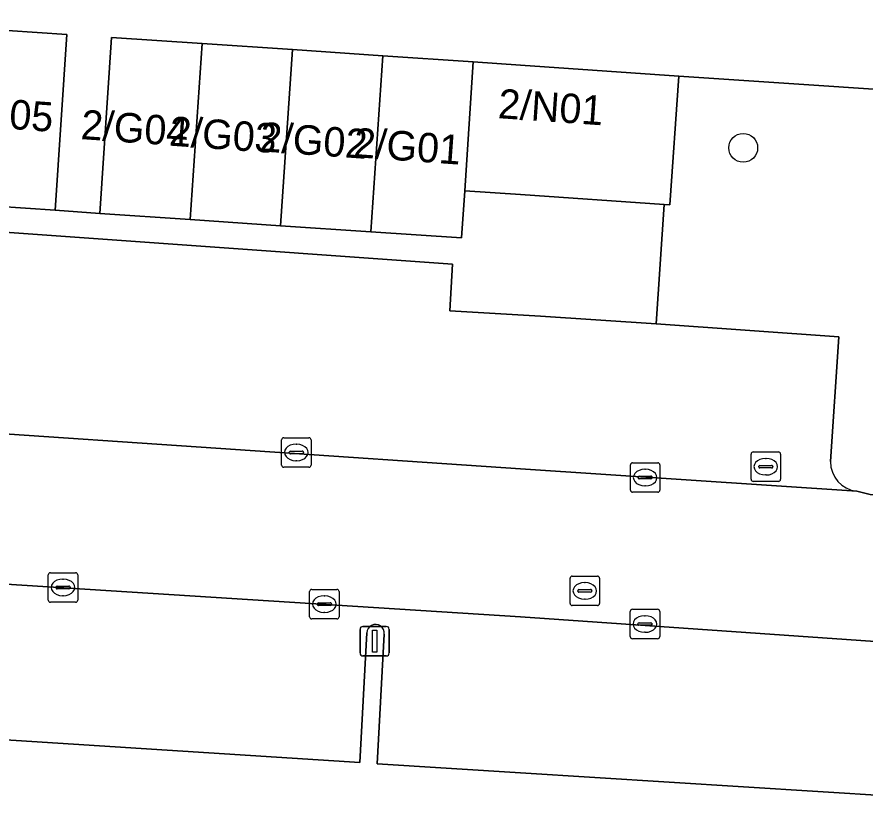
# Model space of a CAD drawing. Extents: x 161848 to 162726, y 385382 to 386521.
# Drawn here: x 161982.91 to 162011.69, y 385866.63 to 385893.06 of the extents above; entities that cross this region are included whole.
import ezdxf

# ---------------------------------------------------------------- set-up
doc = ezdxf.new("R2010")
doc.units = 0
for name, color, linetype in [('IMGEO_Boom', 7, 'Continuous'), ('IMGEO_Brandkraan', 7, 'Continuous'), ('IMGEO_Erf', 7, 'Continuous'), ('IMGEO_Groenvoorziening', 7, 'Continuous'), ('IMGEO_Kolk', 7, 'Continuous'), ('IMGEO_Lichtmast', 7, 'Continuous'), ('IMGEO_Pand', 7, 'Continuous'), ('IMGEO_Pand_nummerreeks', 7, 'Continuous'), ('IMGEO_Parkeervlak_open', 7, 'Continuous'), ('IMGEO_Rijbaan_lokaal_open', 7, 'Continuous'), ('IMGEO_Rioolput', 7, 'Continuous'), ('IMGEO_Voetpad_open', 7, 'Continuous')]:
    doc.layers.add(name, color=color, linetype=linetype)

msp = doc.modelspace()

# ---------------------------------------------------------------- linework, layer by layer
at = {"layer": 'IMGEO_Boom'}
msp.add_circle((162007.553, 385888.622), 0.489, dxfattribs=at)
at = {"layer": 'IMGEO_Brandkraan'}
for p, q in [((162007.818, 385877.377), (162007.818, 385878.229)), ((162007.893, 385878.303), (162008.745, 385878.303)), ((162008.819, 385878.229), (162008.819, 385877.377)), ((162008.12, 385877.846), (162008.518, 385877.846)), ((162008.306, 385878.083), (162008.331, 385878.083)), ((162008.077, 385877.797), (162008.077, 385877.809)), ((162008.515, 385877.76), (162008.117, 385877.76)), ((162008.561, 385877.809), (162008.561, 385877.797)), ((162008.745, 385877.303), (162007.893, 385877.303)), ((162008.329, 385877.523), (162008.304, 385877.523))]:
    msp.add_line(p, q, dxfattribs=at)
for points in [[(162007.818, 385877.377), (162007.818, 385878.229)], [(162007.893, 385878.303), (162008.745, 385878.303)], [(162008.819, 385878.229), (162008.819, 385877.377)], [(162008.745, 385877.303), (162007.893, 385877.303)]]:
    msp.add_lwpolyline(points, dxfattribs=at)
for centre, radius, start, end in [((162007.895, 385878.227), 0.0765, 91.552, 178.448), ((162007.895, 385878.227), 0.0765, 91.552, 178.448), ((162008.743, 385878.227), 0.0765, 1.552, 88.448), ((162008.743, 385878.227), 0.0765, 1.552, 88.448), ((162008.117, 385877.806), 0.0403, 85.8775, 175.7526), ((162008.522, 385877.808), 0.0386, 1.7309, 96.639), ((162008.114, 385877.796), 0.0366, 178.938, 274.7102), ((162008.518, 385877.803), 0.043, 264.8664, 352.4533), ((162007.895, 385877.379), 0.0765, 181.552, 268.448), ((162007.895, 385877.379), 0.0765, 181.552, 268.448), ((162008.743, 385877.379), 0.0765, 271.552, 358.448), ((162008.743, 385877.379), 0.0765, 271.552, 358.448)]:
    msp.add_arc(centre, radius, start, end, dxfattribs=at)
for centre, major_axis, ratio, start_param, end_param in [((162008.305, 385877.803), (-0.387, 0.002), 0.722429, 4.712389, 7.853982), ((162008.33, 385877.803), (-0.39, 0.002), 0.717154, 1.570796, 4.712389)]:
    msp.add_ellipse(centre, major_axis=major_axis, ratio=ratio, start_param=start_param, end_param=end_param, dxfattribs=at)
at = {"layer": 'IMGEO_Erf'}
msp.add_lwpolyline([(161964.413, 385968.919), (161959.389, 385894.166), (161966.417, 385893.698), (161969.448, 385893.493), (161972.48, 385893.288), (161975.512, 385893.084), (161978.543, 385892.879), (161981.575, 385892.674), (161984.606, 385892.469), (161984.206, 385886.51), (161985.726, 385886.39), (161986.122, 385892.367), (161989.19, 385892.16), (161992.258, 385891.952), (161995.326, 385891.745), (161998.394, 385891.537), (162000, 385891.426), (162005.37, 385891.056), (162016.387, 385890.314), (162021.428, 385965.253)], dxfattribs=at)
at = {"layer": 'IMGEO_Groenvoorziening'}
msp.add_lwpolyline([(162011.406, 385876.97), (162011.857, 385876.854), (162014.191, 385876.692), (162015.241, 385876.631), (162015.467, 385876.641), (162016.387, 385890.314), (162005.37, 385891.056), (162005.066, 385886.685), (162004.876, 385886.698), (162004.598, 385882.651), (162010.797, 385882.214), (162010.509, 385877.98)], dxfattribs=at)
msp.add_arc((162011.532, 385877.985), 1.023, 180.2916, 262.9262, dxfattribs=at)
at = {"layer": 'IMGEO_Kolk'}
for p, q in [((161991.891, 385877.859), (161991.891, 385878.711)), ((161991.966, 385878.785), (161992.818, 385878.785)), ((161992.892, 385878.711), (161992.892, 385877.859)), ((161992.379, 385878.565), (161992.404, 385878.565)), ((161992.15, 385878.279), (161992.15, 385878.291)), ((161992.588, 385878.242), (161992.19, 385878.242)), ((161992.193, 385878.328), (161992.591, 385878.328)), ((161992.634, 385878.291), (161992.634, 385878.279)), ((161992.402, 385878.005), (161992.377, 385878.005)), ((162003.724, 385877.009), (162003.724, 385877.861)), ((162003.799, 385877.935), (162004.651, 385877.935)), ((162004.725, 385877.861), (162004.725, 385877.009)), ((161992.818, 385877.785), (161991.966, 385877.785)), ((162004.212, 385877.715), (162004.237, 385877.715)), ((162003.983, 385877.429), (162003.983, 385877.441)), ((162004.421, 385877.392), (162004.023, 385877.392)), ((162004.026, 385877.478), (162004.424, 385877.478)), ((162004.467, 385877.441), (162004.467, 385877.429)), ((162004.235, 385877.155), (162004.21, 385877.155)), ((162004.651, 385876.935), (162003.799, 385876.935)), ((161983.973, 385873.28), (161983.973, 385874.132)), ((161984.048, 385874.206), (161984.9, 385874.206)), ((161984.974, 385874.132), (161984.974, 385873.28)), ((161984.461, 385873.986), (161984.486, 385873.986)), ((161984.232, 385873.7), (161984.232, 385873.712)), ((161984.67, 385873.663), (161984.272, 385873.663)), ((161984.275, 385873.749), (161984.673, 385873.749)), ((161984.716, 385873.712), (161984.716, 385873.7)), ((161992.841, 385872.713), (161992.841, 385873.565)), ((161992.916, 385873.639), (161993.768, 385873.639)), ((161993.842, 385873.565), (161993.842, 385872.713)), ((161984.484, 385873.426), (161984.459, 385873.426)), ((161993.329, 385873.419), (161993.354, 385873.419)), ((161984.9, 385873.206), (161984.048, 385873.206)), ((161993.1, 385873.133), (161993.1, 385873.145)), ((161993.538, 385873.096), (161993.14, 385873.096)), ((161993.143, 385873.182), (161993.541, 385873.182)), ((161993.584, 385873.145), (161993.584, 385873.133)), ((162003.792, 385872.964), (162004.644, 385872.964)), ((161993.352, 385872.859), (161993.327, 385872.859)), ((162003.717, 385872.038), (162003.717, 385872.89)), ((162004.205, 385872.744), (162004.23, 385872.744)), ((162004.718, 385872.89), (162004.718, 385872.038)), ((161993.768, 385872.639), (161992.916, 385872.639)), ((162003.976, 385872.458), (162003.976, 385872.47)), ((162004.414, 385872.421), (162004.016, 385872.421)), ((162004.019, 385872.507), (162004.417, 385872.507)), ((162004.46, 385872.47), (162004.46, 385872.458)), ((162004.228, 385872.184), (162004.203, 385872.184)), ((162004.644, 385871.964), (162003.792, 385871.964))]:
    msp.add_line(p, q, dxfattribs=at)
for points in [[(161991.891, 385877.859), (161991.891, 385878.711)], [(161991.966, 385878.785), (161992.818, 385878.785)], [(161992.892, 385878.711), (161992.892, 385877.859)], [(162003.724, 385877.009), (162003.724, 385877.861)], [(162003.799, 385877.935), (162004.651, 385877.935)], [(162004.725, 385877.861), (162004.725, 385877.009)], [(161992.818, 385877.785), (161991.966, 385877.785)], [(162004.651, 385876.935), (162003.799, 385876.935)], [(161983.973, 385873.28), (161983.973, 385874.132)], [(161984.048, 385874.206), (161984.9, 385874.206)], [(161984.974, 385874.132), (161984.974, 385873.28)], [(161992.841, 385872.713), (161992.841, 385873.565)], [(161992.916, 385873.639), (161993.768, 385873.639)], [(161993.842, 385873.565), (161993.842, 385872.713)], [(161984.9, 385873.206), (161984.048, 385873.206)], [(162003.792, 385872.964), (162004.644, 385872.964)], [(162003.717, 385872.038), (162003.717, 385872.89)], [(162004.718, 385872.89), (162004.718, 385872.038)], [(161993.768, 385872.639), (161992.916, 385872.639)], [(162004.644, 385871.964), (162003.792, 385871.964)]]:
    msp.add_lwpolyline(points, dxfattribs=at)
for centre, radius, start, end in [((161991.968, 385878.709), 0.0765, 91.552, 178.448), ((161991.968, 385878.709), 0.0765, 91.552, 178.448), ((161992.816, 385878.709), 0.0765, 1.552, 88.448), ((161992.816, 385878.709), 0.0765, 1.552, 88.448), ((161992.19, 385878.288), 0.0403, 85.8775, 175.7526), ((161992.187, 385878.278), 0.0366, 178.938, 274.7102), ((161992.591, 385878.285), 0.043, 264.8664, 352.4533), ((161992.595, 385878.29), 0.0386, 1.7309, 96.639), ((161991.968, 385877.861), 0.0765, 181.552, 268.448), ((161991.968, 385877.861), 0.0765, 181.552, 268.448), ((161992.816, 385877.861), 0.0765, 271.552, 358.448), ((161992.816, 385877.861), 0.0765, 271.552, 358.448), ((162003.801, 385877.859), 0.0765, 91.552, 178.448), ((162003.801, 385877.859), 0.0765, 91.552, 178.448), ((162004.649, 385877.859), 0.0765, 1.552, 88.448), ((162004.649, 385877.859), 0.0765, 1.552, 88.448), ((162004.023, 385877.438), 0.0403, 85.8775, 175.7526), ((162004.02, 385877.428), 0.0366, 178.938, 274.7102), ((162004.424, 385877.435), 0.043, 264.8664, 352.4533), ((162004.428, 385877.44), 0.0386, 1.7309, 96.639), ((162003.801, 385877.011), 0.0765, 181.552, 268.448), ((162003.801, 385877.011), 0.0765, 181.552, 268.448), ((162004.649, 385877.011), 0.0765, 271.552, 358.448), ((162004.649, 385877.011), 0.0765, 271.552, 358.448), ((161984.05, 385874.13), 0.0765, 91.552, 178.448), ((161984.05, 385874.13), 0.0765, 91.552, 178.448), ((161984.898, 385874.13), 0.0765, 1.552, 88.448), ((161984.898, 385874.13), 0.0765, 1.552, 88.448), ((161984.272, 385873.709), 0.0403, 85.8775, 175.7526), ((161984.269, 385873.699), 0.0366, 178.938, 274.7102), ((161984.673, 385873.706), 0.043, 264.8664, 352.4533), ((161984.677, 385873.711), 0.0386, 1.7309, 96.639), ((161992.918, 385873.563), 0.0765, 91.552, 178.448), ((161992.918, 385873.563), 0.0765, 91.552, 178.448), ((161993.766, 385873.563), 0.0765, 1.552, 88.448), ((161993.766, 385873.563), 0.0765, 1.552, 88.448), ((161984.05, 385873.282), 0.0765, 181.552, 268.448), ((161984.05, 385873.282), 0.0765, 181.552, 268.448), ((161984.898, 385873.282), 0.0765, 271.552, 358.448), ((161984.898, 385873.282), 0.0765, 271.552, 358.448), ((161993.14, 385873.142), 0.0403, 85.8775, 175.7526), ((161993.137, 385873.132), 0.0366, 178.938, 274.7102), ((161993.541, 385873.139), 0.043, 264.8664, 352.4533), ((161993.545, 385873.144), 0.0386, 1.7309, 96.639), ((162003.794, 385872.888), 0.0765, 91.552, 178.448), ((162003.794, 385872.888), 0.0765, 91.552, 178.448), ((162004.642, 385872.888), 0.0765, 1.552, 88.448), ((162004.642, 385872.888), 0.0765, 1.552, 88.448), ((161992.918, 385872.715), 0.0765, 181.552, 268.448), ((161992.918, 385872.715), 0.0765, 181.552, 268.448), ((161993.766, 385872.715), 0.0765, 271.552, 358.448), ((161993.766, 385872.715), 0.0765, 271.552, 358.448), ((162004.016, 385872.467), 0.0403, 85.8775, 175.7526), ((162004.013, 385872.457), 0.0366, 178.938, 274.7102), ((162004.417, 385872.464), 0.043, 264.8664, 352.4533), ((162004.421, 385872.469), 0.0386, 1.7309, 96.639), ((162003.794, 385872.04), 0.0765, 181.552, 268.448), ((162003.794, 385872.04), 0.0765, 181.552, 268.448), ((162004.642, 385872.04), 0.0765, 271.552, 358.448), ((162004.642, 385872.04), 0.0765, 271.552, 358.448)]:
    msp.add_arc(centre, radius, start, end, dxfattribs=at)
for centre, major_axis, ratio, start_param, end_param in [((161992.378, 385878.285), (-0.387, 0.002), 0.722429, 4.712389, 7.853982), ((161992.403, 385878.285), (-0.39, 0.002), 0.717154, 1.570796, 4.712389), ((162004.211, 385877.435), (-0.387, 0.002), 0.722429, 4.712389, 7.853982), ((162004.236, 385877.435), (-0.39, 0.002), 0.717154, 1.570796, 4.712389), ((161984.46, 385873.706), (-0.387, 0.002), 0.722429, 4.712389, 7.853982), ((161984.485, 385873.706), (-0.39, 0.002), 0.717154, 1.570796, 4.712389), ((161993.328, 385873.139), (-0.387, 0.002), 0.722429, 4.712389, 7.853982), ((161993.353, 385873.139), (-0.39, 0.002), 0.717154, 1.570796, 4.712389), ((162004.204, 385872.464), (-0.387, 0.002), 0.722429, 4.712389, 7.853982), ((162004.229, 385872.464), (-0.39, 0.002), 0.717154, 1.570796, 4.712389)]:
    msp.add_ellipse(centre, major_axis=major_axis, ratio=ratio, start_param=start_param, end_param=end_param, dxfattribs=at)
at = {"layer": 'IMGEO_Lichtmast'}
for p, q in [((161994.651, 385872.383), (161995.441, 385872.383)), ((161995.441, 385872.383), (161994.651, 385872.383)), ((161994.551, 385871.483), (161994.551, 385872.283)), ((161994.551, 385872.283), (161994.551, 385871.483)), ((161995.541, 385872.283), (161995.541, 385871.483)), ((161995.541, 385871.483), (161995.541, 385872.283)), ((161995.441, 385871.383), (161994.651, 385871.383)), ((161994.651, 385871.383), (161995.441, 385871.383))]:
    msp.add_line(p, q, dxfattribs=at)
msp.add_lwpolyline([(161994.971, 385872.258), (161995.121, 385872.258), (161995.121, 385871.508), (161994.971, 385871.508), (161994.971, 385872.258)], dxfattribs=at)
for centre, start, end in [((161994.651, 385872.283), 90, 180), ((161994.651, 385872.283), 90, 180), ((161995.441, 385872.283), 0, 90), ((161995.441, 385872.283), 360, 90), ((161994.651, 385871.483), 180, 270), ((161994.651, 385871.483), 180, 270), ((161995.441, 385871.483), 270, 0), ((161995.441, 385871.483), 270, 0)]:
    msp.add_arc(centre, 0.1, start, end, dxfattribs=at)
at = {"layer": 'IMGEO_Pand'}
for points in [[(161984.206, 385886.51), (161984.606, 385892.469), (161981.575, 385892.674), (161981.172, 385886.714)], [(161988.786, 385886.185), (161989.19, 385892.16), (161986.122, 385892.367), (161985.726, 385886.39)], [(161991.854, 385885.98), (161992.258, 385891.952), (161989.19, 385892.16), (161988.786, 385886.185)], [(161994.922, 385885.775), (161995.326, 385891.745), (161992.258, 385891.952), (161991.854, 385885.98)], [(161998.394, 385891.537), (161995.326, 385891.745), (161994.922, 385885.775), (161997.99, 385885.57), (161998.103, 385887.168)], [(161998.103, 385887.168), (162000, 385887.036), (162004.876, 385886.698), (162005.066, 385886.685), (162005.37, 385891.056), (162000, 385891.426), (161998.394, 385891.537)]]:
    msp.add_lwpolyline(points, close=True, dxfattribs=at)
at = {"layer": 'IMGEO_Parkeervlak_open'}
for points in [[(162010.797, 385882.214), (162004.598, 385882.651), (162000.678, 385882.914), (161997.596, 385883.095), (161997.689, 385884.679), (161966.198, 385886.924), (161965.883, 385882.139), (161965.858, 385881.363)], [(162010.509, 385877.98), (162010.797, 385882.214)], [(161964.413, 385880.209), (161980.639, 385879.037), (162000, 385877.736), (162011.406, 385876.97)], [(162013.661, 385871.754), (162000, 385872.704), (161960.809, 385875.198)], [(161974.795, 385873.433), (161974.565, 385869.042), (161994.54, 385867.767), (161994.78, 385872.163)], [(161995.37, 385872.124), (161995.137, 385867.724), (162000, 385867.419), (162012.612, 385866.629), (162012.591, 385868.514), (162012.715, 385870.817)]]:
    msp.add_lwpolyline(points, dxfattribs=at)
for centre, radius, start, end in [((162011.532, 385877.985), 1.023, 180.2916, 262.9262), ((161995.076, 385872.154), 0.296, 354.2171, 178.2192)]:
    msp.add_arc(centre, radius, start, end, dxfattribs=at)
at = {"layer": 'IMGEO_Rijbaan_lokaal_open'}
for points in [[(161956.869, 385886.598), (161951.972, 385886.976), (161951.694, 385882.724), (161951.359, 385877.618), (161951.247, 385875.773), (161960.809, 385875.198), (162000, 385872.704), (162013.661, 385871.754), (162013.838, 385871.739), (162014.191, 385876.692), (162011.857, 385876.854), (162011.406, 385876.97), (162000, 385877.736)], [(162000, 385877.736), (161980.639, 385879.037), (161964.413, 385880.209), (161962.332, 385880.359)]]:
    msp.add_lwpolyline(points, dxfattribs=at)
at = {"layer": 'IMGEO_Rioolput'}
for p, q in [((162001.677, 385873.164), (162001.677, 385874.016)), ((162001.752, 385874.09), (162002.604, 385874.09)), ((162002.165, 385873.87), (162002.19, 385873.87)), ((162002.678, 385874.016), (162002.678, 385873.164)), ((162001.936, 385873.584), (162001.936, 385873.596)), ((162002.374, 385873.547), (162001.976, 385873.547)), ((162001.979, 385873.633), (162002.377, 385873.633)), ((162002.42, 385873.596), (162002.42, 385873.584)), ((162002.188, 385873.31), (162002.163, 385873.31)), ((162002.604, 385873.09), (162001.752, 385873.09))]:
    msp.add_line(p, q, dxfattribs=at)
for points in [[(162001.677, 385873.164), (162001.677, 385874.016)], [(162001.752, 385874.09), (162002.604, 385874.09)], [(162002.678, 385874.016), (162002.678, 385873.164)], [(162002.604, 385873.09), (162001.752, 385873.09)]]:
    msp.add_lwpolyline(points, dxfattribs=at)
for centre, radius, start, end in [((162001.754, 385874.014), 0.0765, 91.552, 178.448), ((162001.754, 385874.014), 0.0765, 91.552, 178.448), ((162002.602, 385874.014), 0.0765, 1.552, 88.448), ((162002.602, 385874.014), 0.0765, 1.552, 88.448), ((162001.976, 385873.593), 0.0403, 85.8775, 175.7526), ((162001.973, 385873.583), 0.0366, 178.938, 274.7102), ((162002.377, 385873.59), 0.043, 264.8664, 352.4533), ((162002.381, 385873.595), 0.0386, 1.7309, 96.639), ((162001.754, 385873.166), 0.0765, 181.552, 268.448), ((162001.754, 385873.166), 0.0765, 181.552, 268.448), ((162002.602, 385873.166), 0.0765, 271.552, 358.448), ((162002.602, 385873.166), 0.0765, 271.552, 358.448)]:
    msp.add_arc(centre, radius, start, end, dxfattribs=at)
for centre, major_axis, ratio, start_param, end_param in [((162002.164, 385873.59), (-0.387, 0.002), 0.722429, 4.712389, 7.853982), ((162002.189, 385873.59), (-0.39, 0.002), 0.717154, 1.570796, 4.712389)]:
    msp.add_ellipse(centre, major_axis=major_axis, ratio=ratio, start_param=start_param, end_param=end_param, dxfattribs=at)
at = {"layer": 'IMGEO_Voetpad_open'}
msp.add_lwpolyline([(161975.109, 385887.121), (161972.077, 385887.324), (161969.045, 385887.527), (161966.25, 385887.715), (161966.198, 385886.924), (161997.689, 385884.679), (161997.596, 385883.095), (162000.678, 385882.914), (162004.598, 385882.651), (162004.876, 385886.698), (162000, 385887.036), (161998.103, 385887.168), (161997.99, 385885.57), (161994.922, 385885.775), (161991.854, 385885.98), (161988.786, 385886.185), (161985.726, 385886.39), (161984.206, 385886.51), (161981.172, 385886.714), (161978.14, 385886.917)], close=True, dxfattribs=at)
for points in [[(161994.78, 385872.163), (161994.54, 385867.767), (161974.565, 385869.042), (161974.795, 385873.433)], [(162012.715, 385870.817), (162012.591, 385868.514), (162012.612, 385866.629), (162000, 385867.419), (161995.137, 385867.724), (161995.37, 385872.124)]]:
    msp.add_lwpolyline(points, dxfattribs=at)
msp.add_arc((161995.076, 385872.154), 0.296, 354.2171, 178.2192, dxfattribs=at)

# ---------------------------------------------------------------- texts
at = {"layer": 'IMGEO_Pand_nummerreeks'}
for s, rotation, p in [('2/N01', 356.0435, (161999.213, 385889.63)), ('2/G05', 355.9392, (161980.475, 385889.42)), ('2/G04', 355.9392, (161985.055, 385888.92)), ('2/G03', 355.9392, (161988.053, 385888.698)), ('2/G02', 355.9392, (161991.128, 385888.504)), ('2/G01', 355.9392, (161994.307, 385888.308))]:
    msp.add_text(s, height=1, rotation=rotation, dxfattribs=at).set_placement(p)

doc.saveas('drawing.dxf')
